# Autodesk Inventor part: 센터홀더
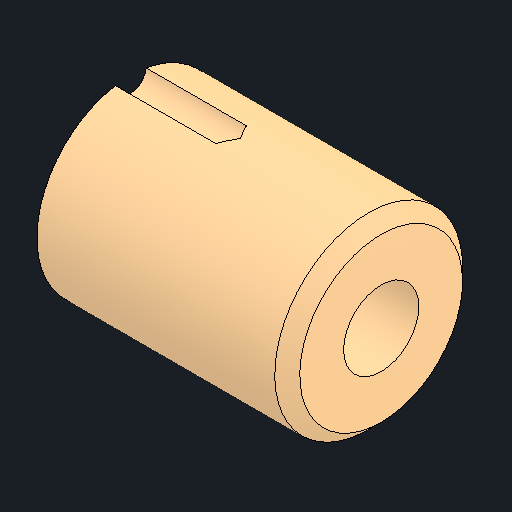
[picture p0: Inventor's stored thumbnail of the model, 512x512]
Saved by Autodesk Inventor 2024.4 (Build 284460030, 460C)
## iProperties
Created: 2026-08
Part Number: 센터홀더
Material: 강철, 연강
Document SubType Name: Modeling
Designer: user
Density: 7.86 g/cm^3
Appearance: 기본값
Author: jhkim
Sending System: Autodesk Inventor 2027
Preprocessor: ST-DEVELOPER v20.1
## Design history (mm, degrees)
feature "솔리드1"
node "솔리드2"
